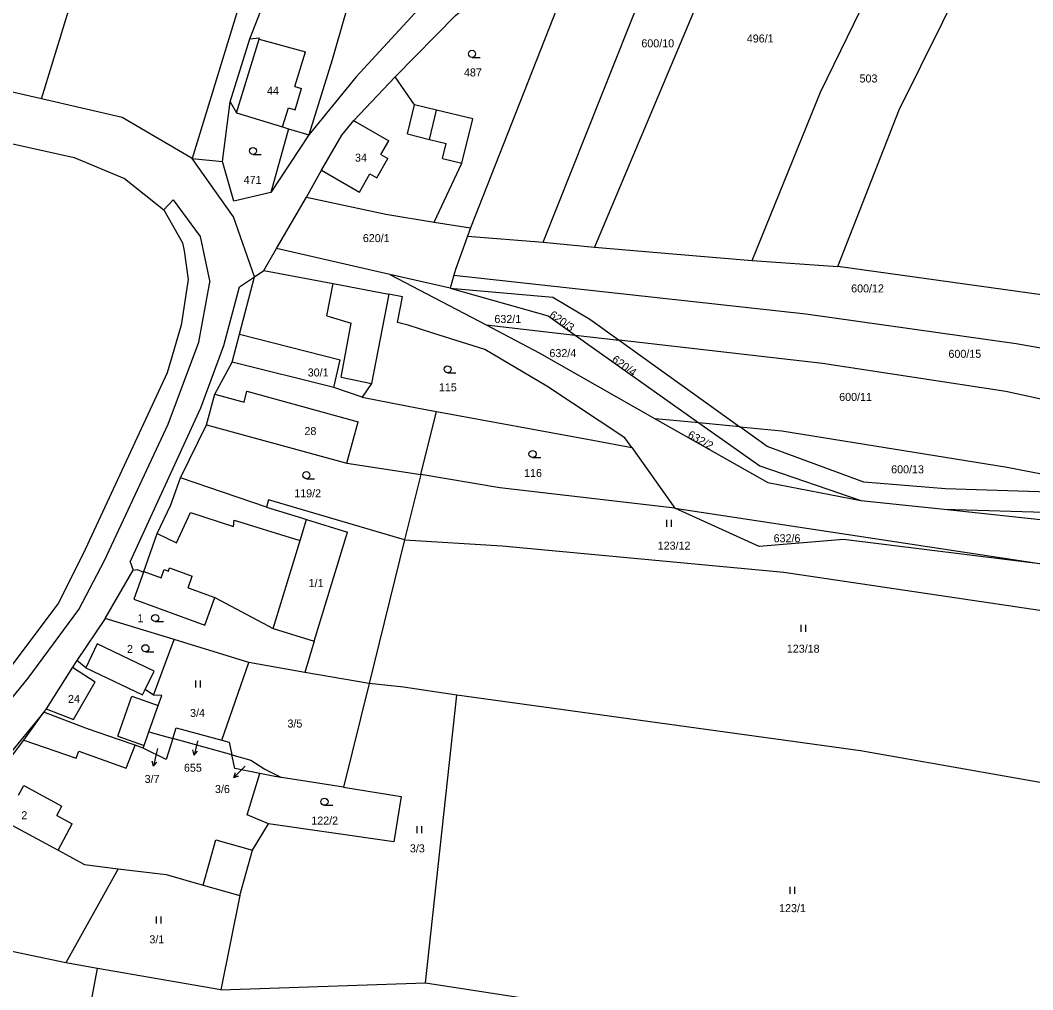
# Model space of a CAD drawing. Extents: x -746176 to -739709, y -1128407 to -1124482.
# Drawn here: x -742817.8 to -742602.7, y -1127345.9 to -1127139.9 of the extents above; entities that cross this region are included whole.
import ezdxf

# ---------------------------------------------------------------- set-up
doc = ezdxf.new("R2010")
doc.units = 0
for name, color, linetype in [('Hranice parcel', 7, 'Continuous'), ('Parcelní čísla', 7, 'Continuous'), ('Pop  PČ popisy', 7, 'Continuous'), ('Vnitřní kresba', 7, 'Continuous'), ('Značky kultur', 7, 'Continuous')]:
    doc.layers.add(name, color=color, linetype=linetype)

msp = doc.modelspace()

# ---------------------------------------------------------------- linework, layer by layer
at = {"layer": 'Hranice parcel'}
for p, q in [((-742734.68, -1127016.73), (-742781.25, -1127169.22)), ((-742694.65, -1127113.94), (-742722.13, -1127184.01)), ((-742813.25, -1127156.61), (-742828.27, -1127153.14)), ((-742774.85, -1127169.87), (-742773.17, -1127157.23)), ((-742756.51, -1127164.2), (-742764.59, -1127176.5)), ((-742781.25, -1127169.22), (-742774.85, -1127169.87)), ((-742763.32, -1127188.38), (-742756.98, -1127177.44)), ((-742729.83, -1127182.75), (-742722.13, -1127184.01)), ((-742722.13, -1127184.01), (-742722.77, -1127185.76)), ((-742722.77, -1127185.76), (-742706.71, -1127187.05)), ((-742766.04, -1127193.06), (-742763.32, -1127188.38)), ((-742739.28, -1127193.88), (-742763.32, -1127188.38)), ((-742706.71, -1127187.05), (-742695.82, -1127188.09)), ((-742662.31, -1127190.95), (-742644.1, -1127192.22)), ((-742566.48, -1127203.04), (-742644.1, -1127192.22)), ((-742768.06, -1127194.37), (-742766.04, -1127193.06)), ((-742726.46, -1127196.81), (-742739.28, -1127193.88)), ((-742739.28, -1127193.88), (-742718.84, -1127204.63)), ((-742725.69, -1127194.04), (-742726.46, -1127196.81)), ((-742726.46, -1127196.81), (-742704.64, -1127198.69)), ((-742718.84, -1127204.63), (-742699.9, -1127206.79)), ((-742699.9, -1127206.79), (-742690.57, -1127207.86)), ((-742699.9, -1127206.79), (-742673.62, -1127225.43)), ((-742690.57, -1127207.86), (-742664.96, -1127226.26)), ((-742732.7, -1127236.41), (-742729.39, -1127223.02)), ((-742729.39, -1127223.02), (-742696.14, -1127229.14)), ((-742673.62, -1127225.43), (-742682.93, -1127224.54)), ((-742783.76, -1127237.1), (-742778.23, -1127225.83)), ((-742664.96, -1127226.26), (-742673.62, -1127225.43)), ((-742696.14, -1127229.14), (-742687.9, -1127230.66)), ((-742687.9, -1127230.66), (-742678.76, -1127243.56)), ((-742732.7, -1127236.41), (-742736.14, -1127250.3)), ((-742639.2, -1127241.9), (-742621.56, -1127243.8)), ((-742678.76, -1127243.56), (-742598.97, -1127255.65)), ((-742621.56, -1127243.8), (-742574.02, -1127248.78)), ((-742621.56, -1127243.8), (-742577.26, -1127245.05)), ((-742736.14, -1127250.3), (-742743.69, -1127280.81)), ((-742799.73, -1127266.98), (-742805.74, -1127275.9)), ((-742785.11, -1127271.49), (-742799.73, -1127266.98)), ((-742789.51, -1127283.3), (-742785.11, -1127271.49)), ((-742769.26, -1127276.37), (-742785.11, -1127271.49)), ((-742774.96, -1127292.87), (-742769.26, -1127276.37)), ((-742757.36, -1127278.44), (-742769.26, -1127276.37)), ((-742743.69, -1127280.81), (-742757.36, -1127278.44)), ((-742743.69, -1127280.81), (-742749.15, -1127302.87)), ((-742736.37, -1127281.56), (-742743.69, -1127280.81)), ((-742725.03, -1127283.28), (-742736.37, -1127281.56)), ((-742731.72, -1127344.4), (-742725.03, -1127283.28)), ((-742790.45, -1127291.06), (-742785.38, -1127292.47)), ((-742772.81, -1127295.97), (-742785.38, -1127292.47)), ((-742749.15, -1127302.87), (-742762.29, -1127300.78)), ((-742796.97, -1127320.16), (-742808.12, -1127340.19)), ((-742771.16, -1127325.84), (-742775.15, -1127345.88)), ((-742809.96, -1127387.12), (-742801.38, -1127341.35)), ((-742801.38, -1127341.35), (-742808.12, -1127340.19)), ((-742775.15, -1127345.88), (-742801.38, -1127341.35)), ((-742775.15, -1127345.88), (-742731.72, -1127344.4))]:
    msp.add_line(p, q, dxfattribs=at)
for points in [[(-742813.25, -1127156.61), (-742778.25, -1127042.21), (-742763.25, -1126998.63), (-742748.81, -1126966.24)], [(-742656.1, -1127095.61), (-742668.92, -1127124.1), (-742695.82, -1127188.09)], [(-742706.71, -1127187.05), (-742685.41, -1127133.42), (-742671.65, -1127102.1)], [(-742662.31, -1127190.95), (-742647.78, -1127155.16), (-742629.16, -1127116.92), (-742619.79, -1127101.89)], [(-742644.1, -1127192.22), (-742631.06, -1127158.9), (-742603.37, -1127102.87)], [(-742738.13, -1127151.87), (-742725.34, -1127138.85), (-742706.66, -1127123.2), (-742694.65, -1127113.94)], [(-742773.17, -1127157.23), (-742769.01, -1127143.81), (-742766.77, -1127137.99), (-742764.69, -1127131.41), (-742763.33, -1127127.12)], [(-742746.73, -1127131.84), (-742748.92, -1127139.17), (-742751.52, -1127148.31), (-742756.51, -1127164.2)], [(-742731.14, -1127135.75), (-742733.12, -1127137.46), (-742746.45, -1127151.91), (-742756.51, -1127164.2)], [(-742756.98, -1127177.44), (-742753.8, -1127171.75), (-742749.51, -1127164.33), (-742746.92, -1127161.19), (-742738.13, -1127151.87)], [(-742729.83, -1127182.75), (-742723.99, -1127170.28), (-742721.67, -1127160.86), (-742729.37, -1127158.96), (-742734.01, -1127157.82), (-742738.13, -1127151.87)], [(-742781.25, -1127169.22), (-742796.14, -1127160.57), (-742813.25, -1127156.61)], [(-742773.17, -1127157.23), (-742771.82, -1127159.58), (-742762.06, -1127162.55), (-742760.77, -1127162.93), (-742764.59, -1127176.5)], [(-742830.93, -1127163.61), (-742806.35, -1127169.04), (-742795.67, -1127173.47), (-742787.26, -1127180.14), (-742783.29, -1127187.16), (-742782.95, -1127188.88), (-742782.14, -1127194.94), (-742783.62, -1127204.69), (-742786.61, -1127214.77), (-742804.45, -1127253.23), (-742809.73, -1127263.8), (-742820.62, -1127278.32)], [(-742768.06, -1127194.37), (-742772.5, -1127181.64), (-742781.25, -1127169.22)], [(-742764.59, -1127176.5), (-742772.44, -1127178.33), (-742774.85, -1127169.87)], [(-742756.98, -1127177.44), (-742740.1, -1127181.07), (-742729.83, -1127182.75)], [(-742722.77, -1127185.76), (-742725.36, -1127192.86), (-742725.69, -1127194.04)], [(-742695.82, -1127188.09), (-742678.35, -1127189.57), (-742662.31, -1127190.95)], [(-742772.74, -1127212.53), (-742771.21, -1127206.56), (-742768.06, -1127194.37)], [(-742766.04, -1127193.06), (-742751.29, -1127195.85), (-742739.47, -1127198.11)], [(-742725.69, -1127194.04), (-742650.94, -1127202.29), (-742606.23, -1127208.56), (-742569.32, -1127215.09)], [(-742726.46, -1127196.81), (-742705.66, -1127202.71), (-742699.9, -1127206.79)], [(-742739.47, -1127198.11), (-742743.16, -1127217.09), (-742745.13, -1127219.95)], [(-742737.64, -1127204.11), (-742736.58, -1127198.66), (-742739.47, -1127198.11)], [(-742704.64, -1127198.69), (-742696.83, -1127203.36), (-742690.57, -1127207.86)], [(-742719.13, -1127209.84), (-742730.16, -1127206.35), (-742735.37, -1127204.64), (-742737.64, -1127204.11)], [(-742718.84, -1127204.63), (-742707.57, -1127210.55), (-742682.93, -1127224.54)], [(-742572.17, -1127226.73), (-742608.43, -1127218.73), (-742647.39, -1127212.79), (-742690.57, -1127207.86)], [(-742687.9, -1127230.66), (-742689.33, -1127228.64), (-742705.92, -1127217.63), (-742719.13, -1127209.84)], [(-742778.23, -1127225.83), (-742776.45, -1127219.31), (-742772.74, -1127212.53)], [(-742745.13, -1127219.95), (-742751.2, -1127217.94), (-742772.74, -1127212.53)], [(-742745.13, -1127219.95), (-742733.19, -1127222.32), (-742729.39, -1127223.02)], [(-742682.93, -1127224.54), (-742658.99, -1127238.12), (-742639.2, -1127241.9)], [(-742778.23, -1127225.83), (-742748.39, -1127234), (-742732.7, -1127236.41)], [(-742673.62, -1127225.43), (-742660.72, -1127234.58), (-742639.2, -1127241.9)], [(-742664.96, -1127226.26), (-742655.98, -1127227.12), (-742608.13, -1127234.85), (-742577.19, -1127240.89)], [(-742577.19, -1127240.89), (-742621.26, -1127239.44), (-742638.6, -1127238), (-742659.14, -1127230.44), (-742664.96, -1127226.26)], [(-742791.59, -1127257.13), (-742791.56, -1127257.04), (-742788.68, -1127248.97), (-742785.8, -1127242.82), (-742783.76, -1127237.1)], [(-742736.14, -1127250.3), (-742765.02, -1127241.79), (-742765.5, -1127243.32), (-742783.76, -1127237.1)], [(-742678.76, -1127243.56), (-742715.93, -1127239.23), (-742732.7, -1127236.41)], [(-742598.97, -1127255.65), (-742642.9, -1127250.2), (-742660.81, -1127251.7), (-742678.76, -1127243.56)], [(-742736.14, -1127250.3), (-742715.39, -1127251.55), (-742655.59, -1127257.18), (-742597.39, -1127265.81), (-742577.59, -1127269.9)], [(-742799.73, -1127266.98), (-742793.82, -1127256.75), (-742792.94, -1127256.6), (-742791.59, -1127257.13)], [(-742791.59, -1127257.13), (-742793.68, -1127262.86), (-742778.58, -1127268.39), (-742776.45, -1127262.56), (-742764.09, -1127269.15), (-742755.34, -1127271.83), (-742757.36, -1127278.44)], [(-742789.51, -1127283.3), (-742791.23, -1127282.07), (-742789.37, -1127278.2), (-742801.41, -1127272.41), (-742803.83, -1127277.46), (-742805.74, -1127275.9)], [(-742805.74, -1127275.9), (-742806.68, -1127277.37), (-742812.31, -1127286.21), (-742812.76, -1127286.93)], [(-742790.45, -1127291.06), (-742788.48, -1127285.47), (-742787.73, -1127283.35), (-742789.51, -1127283.3)], [(-742583.12, -1127305.02), (-742639.33, -1127295.15), (-742725.03, -1127283.28)], [(-742812.76, -1127286.93), (-742822.58, -1127298.79), (-742825.03, -1127301.3)], [(-742791.67, -1127294.54), (-742793.35, -1127293.9), (-742796.91, -1127292.72), (-742803.47, -1127290.41), (-742812.76, -1127286.93)], [(-742791.67, -1127294.54), (-742791.47, -1127293.96), (-742790.45, -1127291.06)], [(-742785.38, -1127292.47), (-742784.67, -1127290.21), (-742774.96, -1127292.87)], [(-742785.38, -1127292.47), (-742786.8, -1127296.94), (-742791.67, -1127294.54)], [(-742774.96, -1127292.87), (-742773.39, -1127293.3), (-742772.81, -1127295.97)], [(-742772.81, -1127295.97), (-742768.78, -1127297.1), (-742765.8, -1127299.02), (-742762.29, -1127300.78)], [(-742766.91, -1127299.92), (-742772.19, -1127298.87), (-742772.81, -1127295.97)], [(-742765.04, -1127310.66), (-742769.57, -1127308.75), (-742766.91, -1127299.92)], [(-742762.29, -1127300.78), (-742763.69, -1127300.56), (-742766.91, -1127299.92)], [(-742825.03, -1127301.3), (-742822.92, -1127302.22), (-742825.81, -1127307.59), (-742809.73, -1127316.24), (-742804.13, -1127319.29), (-742796.97, -1127320.16)], [(-742749.15, -1127302.87), (-742736.87, -1127304.83), (-742738.41, -1127314.45), (-742765.04, -1127310.66)], [(-742771.16, -1127325.84), (-742768.44, -1127316.21), (-742765.04, -1127310.66)], [(-742796.97, -1127320.16), (-742786.76, -1127321.38), (-742778.95, -1127323.64), (-742771.16, -1127325.84)], [(-742808.12, -1127340.19), (-742832.48, -1127335.04), (-742837.98, -1127333.31), (-742850.51, -1127328.29)], [(-742731.72, -1127344.4), (-742692.68, -1127350.41), (-742637.04, -1127361.12)]]:
    msp.add_lwpolyline(points, dxfattribs=at)
at = {"layer": 'Pop  PČ popisy'}
for p, q in [((-742780.13, -1127293.1), (-742780.86, -1127296.01)), ((-742780.11, -1127292.99), (-742780.13, -1127293.1)), ((-742788.81, -1127295.45), (-742789.48, -1127298.37)), ((-742788.62, -1127294.6), (-742788.81, -1127295.45)), ((-742780.86, -1127296.01), (-742781.1, -1127294.92)), ((-742780.86, -1127296.01), (-742780.13, -1127295.16)), ((-742789.48, -1127298.37), (-742789.75, -1127297.29)), ((-742789.48, -1127298.37), (-742788.77, -1127297.51)), ((-742770.29, -1127298.67), (-742772.45, -1127300.76)), ((-742772.45, -1127300.76), (-742772.08, -1127299.7)), ((-742772.45, -1127300.76), (-742771.38, -1127300.42)), ((-742769.98, -1127298.38), (-742770.29, -1127298.67))]:
    msp.add_line(p, q, dxfattribs=at)
at = {"layer": 'Vnitřní kresba'}
for p, q in [((-742771.82, -1127159.58), (-742767.06, -1127143.93)), ((-742769.01, -1127143.81), (-742766.96, -1127143.59)), ((-742767.06, -1127143.93), (-742766.96, -1127143.59)), ((-742767.06, -1127143.93), (-742757.2, -1127146.56)), ((-742759.44, -1127153.94), (-742757.2, -1127146.56)), ((-742759.44, -1127153.94), (-742758.01, -1127154.38)), ((-742759.39, -1127158.92), (-742758.01, -1127154.38)), ((-742762.06, -1127162.55), (-742760.82, -1127158.48)), ((-742760.82, -1127158.48), (-742759.39, -1127158.92)), ((-742735.55, -1127164.03), (-742734.01, -1127157.82)), ((-742730.82, -1127165.2), (-742729.37, -1127158.96)), ((-742746.92, -1127161.19), (-742746.49, -1127161.44)), ((-742746.49, -1127161.44), (-742739.46, -1127165.49)), ((-742760.77, -1127162.93), (-742756.51, -1127164.2)), ((-742735.55, -1127164.03), (-742730.82, -1127165.2)), ((-742741.16, -1127168.43), (-742739.46, -1127165.49)), ((-742730.82, -1127165.2), (-742727.31, -1127166.06)), ((-742728.1, -1127169.27), (-742727.31, -1127166.06)), ((-742742.03, -1127173.35), (-742739.69, -1127169.28)), ((-742741.16, -1127168.43), (-742739.69, -1127169.28)), ((-742728.1, -1127169.27), (-742723.99, -1127170.28)), ((-742753.8, -1127171.75), (-742745.75, -1127176.39)), ((-742745.75, -1127176.39), (-742743.5, -1127172.5)), ((-742743.5, -1127172.5), (-742742.03, -1127173.35)), ((-742787.26, -1127180.14), (-742785.27, -1127178.06)), ((-742785.27, -1127178.06), (-742779.59, -1127185.83)), ((-742779.59, -1127185.83), (-742777.49, -1127195.5)), ((-742771.22, -1127196.55), (-742768.06, -1127194.37)), ((-742779.83, -1127208.27), (-742777.49, -1127195.5)), ((-742774.52, -1127209.02), (-742771.22, -1127196.55)), ((-742752.68, -1127202.66), (-742751.29, -1127195.85)), ((-742752.68, -1127202.66), (-742747.52, -1127204.24)), ((-742749.65, -1127215.74), (-742747.52, -1127204.24)), ((-742771.21, -1127206.56), (-742749.8, -1127212.05)), ((-742786.33, -1127225.73), (-742779.83, -1127208.27)), ((-742779.4, -1127222.27), (-742774.52, -1127209.02)), ((-742751.2, -1127217.94), (-742749.8, -1127212.05)), ((-742749.65, -1127215.74), (-742743.16, -1127217.09)), ((-742770.25, -1127221), (-742769.62, -1127218.71)), ((-742769.62, -1127218.71), (-742745.98, -1127225.18)), ((-742776.45, -1127219.31), (-742770.25, -1127221)), ((-742794.47, -1127254.98), (-742779.4, -1127222.27)), ((-742748.39, -1127234), (-742745.98, -1127225.18)), ((-742799.87, -1127254.66), (-742786.33, -1127225.73)), ((-742784.62, -1127250.9), (-742781.6, -1127244.46)), ((-742781.6, -1127244.46), (-742772.5, -1127247.48)), ((-742765.5, -1127243.32), (-742757.86, -1127245.7)), ((-742772.5, -1127247.48), (-742772.35, -1127246.12)), ((-742772.35, -1127246.12), (-742759.55, -1127250.04)), ((-742758.36, -1127250.41), (-742757, -1127245.96)), ((-742757.86, -1127245.7), (-742757, -1127245.96)), ((-742757, -1127245.96), (-742748.25, -1127248.63)), ((-742755.34, -1127271.83), (-742748.25, -1127248.63)), ((-742788.68, -1127248.97), (-742784.62, -1127250.9)), ((-742764.09, -1127269.15), (-742758.36, -1127250.41)), ((-742759.55, -1127250.04), (-742758.36, -1127250.41)), ((-742805.34, -1127265.1), (-742799.87, -1127254.66)), ((-742794.47, -1127254.98), (-742793.82, -1127256.75)), ((-742791.56, -1127257.04), (-742787.87, -1127258.39)), ((-742787.87, -1127258.39), (-742787.22, -1127256.6)), ((-742787.22, -1127256.6), (-742786.32, -1127256.93)), ((-742786.32, -1127256.93), (-742786.08, -1127256.25)), ((-742786.08, -1127256.25), (-742781.24, -1127258.02)), ((-742782.14, -1127260.48), (-742781.24, -1127258.02)), ((-742782.14, -1127260.48), (-742776.45, -1127262.56)), ((-742816.12, -1127279.67), (-742805.34, -1127265.1)), ((-742806.68, -1127277.37), (-742801.85, -1127280.44)), ((-742803.83, -1127277.46), (-742791.8, -1127283.24)), ((-742828.54, -1127294.89), (-742816.12, -1127279.67)), ((-742806.5, -1127288.47), (-742801.85, -1127280.44)), ((-742791.8, -1127283.24), (-742791.23, -1127282.07)), ((-742797.08, -1127291.98), (-742794.09, -1127283.5)), ((-742794.09, -1127283.5), (-742788.48, -1127285.47)), ((-742817.01, -1127292.85), (-742812.76, -1127286.93)), ((-742812.31, -1127286.21), (-742806.5, -1127288.47)), ((-742821.15, -1127298.28), (-742817.01, -1127292.85)), ((-742817.01, -1127292.85), (-742805.94, -1127296.71)), ((-742797.08, -1127291.98), (-742791.47, -1127293.96)), ((-742795.29, -1127298.83), (-742793.35, -1127293.9)), ((-742805.94, -1127296.71), (-742805.36, -1127295.2)), ((-742805.36, -1127295.2), (-742795.29, -1127298.83)), ((-742818.13, -1127304.52), (-742817.03, -1127302.49)), ((-742817.03, -1127302.49), (-742808.92, -1127306.85)), ((-742810.01, -1127308.88), (-742808.92, -1127306.85)), ((-742810.01, -1127308.88), (-742806.73, -1127310.65)), ((-742809.73, -1127316.24), (-742806.73, -1127310.65)), ((-742778.95, -1127323.64), (-742776.23, -1127314.01)), ((-742776.23, -1127314.01), (-742768.44, -1127316.21))]:
    msp.add_line(p, q, dxfattribs=at)
at = {"layer": 'Značky kultur'}
for p, q in [((-742721.82, -1127147.76), (-742720.07, -1127147.76)), ((-742768.34, -1127168.4), (-742766.59, -1127168.4)), ((-742727.01, -1127214.79), (-742725.26, -1127214.79)), ((-742708.97, -1127232.8), (-742707.22, -1127232.8)), ((-742757, -1127237.29), (-742755.25, -1127237.29)), ((-742680.47, -1127247.53), (-742680.47, -1127246.03)), ((-742679.47, -1127247.53), (-742679.47, -1127246.03)), ((-742789.12, -1127267.66), (-742787.37, -1127267.66)), ((-742651.93, -1127269.85), (-742651.93, -1127268.35)), ((-742650.93, -1127269.85), (-742650.93, -1127268.35)), ((-742791.19, -1127274.07), (-742789.44, -1127274.07)), ((-742780.51, -1127281.67), (-742780.51, -1127280.17)), ((-742779.51, -1127281.67), (-742779.51, -1127280.17)), ((-742753.16, -1127306.69), (-742751.41, -1127306.69)), ((-742733.48, -1127312.65), (-742733.48, -1127311.15)), ((-742732.48, -1127312.65), (-742732.48, -1127311.15)), ((-742654.25, -1127325.53), (-742654.25, -1127324.03)), ((-742653.25, -1127325.53), (-742653.25, -1127324.03)), ((-742788.86, -1127331.79), (-742788.86, -1127330.29)), ((-742787.86, -1127331.79), (-742787.86, -1127330.29))]:
    msp.add_line(p, q, dxfattribs=at)
for centre in [(-742721.82, -1127147.01), (-742768.34, -1127167.65), (-742727.01, -1127214.04), (-742708.97, -1127232.05), (-742757, -1127236.54), (-742789.12, -1127266.91), (-742791.19, -1127273.32), (-742753.16, -1127305.94)]:
    msp.add_circle(centre, 0.75, dxfattribs=at)

# ---------------------------------------------------------------- texts
at = {"layer": 'Parcelní čísla'}
for s, p in [('496/1', (-742663.45, -1127144.6)), ('600/10', (-742685.85, -1127145.63)), ('487', (-742723.53, -1127151.82)), ('503', (-742639.51, -1127153.1)), ('44', (-742765.38, -1127155.69)), ('34', (-742746.68, -1127169.92)), ('471', (-742770.32, -1127174.65)), ('620/1', (-742745.01, -1127187.02)), ('600/12', (-742641.29, -1127197.71)), ('632/1', (-742717.07, -1127204.21)), ('632/4', (-742705.38, -1127211.46)), ('600/15', (-742620.62, -1127211.61)), ('30/1', (-742756.72, -1127215.57)), ('115', (-742728.86, -1127218.73)), ('600/11', (-742643.83, -1127220.77)), ('28', (-742757.41, -1127228.02)), ('116', (-742710.76, -1127236.93)), ('600/13', (-742632.79, -1127236.15)), ('119/2', (-742759.58, -1127241.25)), ('123/12', (-742682.38, -1127252.36)), ('632/6', (-742657.76, -1127250.8)), ('1/1', (-742756.53, -1127260.32)), ('1', (-742792.88, -1127267.8)), ('123/18', (-742654.95, -1127274.26)), ('2', (-742795.11, -1127274.31)), ('24', (-742807.64, -1127284.94)), ('3/4', (-742781.71, -1127287.92)), ('3/5', (-742761.02, -1127290.17)), ('655', (-742783.01, -1127299.56)), ('3/7', (-742791.36, -1127301.94)), ('3/6', (-742776.42, -1127304.09)), ('2', (-742817.55, -1127309.65)), ('122/2', (-742755.96, -1127310.79)), ('3/3', (-742735.02, -1127316.7)), ('123/1', (-742656.59, -1127329.4)), ('3/1', (-742790.35, -1127336.02))]:
    msp.add_text(s, height=1.7, dxfattribs=at).set_placement(p)
for s, rotation, p in [('620/3', 325, (-742705.53, -1127202.84)), ('620/4', 324, (-742692.27, -1127212.3)), ('632/2', 331, (-742676.16, -1127228.45))]:
    msp.add_text(s, height=1.7, rotation=rotation, dxfattribs=at).set_placement(p)

doc.saveas('drawing.dxf')
